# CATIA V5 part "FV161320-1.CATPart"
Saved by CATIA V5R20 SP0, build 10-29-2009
Part number: FV161320-1
Revision: ANY
Definition: UNKNOWN
Nomenclature: FV161320-1
Source: Unknown
Bounding box of the stored display mesh (mm): x -8 to 8, y -20 to 0, z -8 to 8
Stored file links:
  C:\Users\Utente\Desktop\IO LAVORO\3D X SITO CF\CUMSA\3D files FV\FV 161320\FV161320-1.CATPart
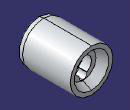
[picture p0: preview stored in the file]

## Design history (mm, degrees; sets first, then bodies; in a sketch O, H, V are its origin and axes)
Body1 "Cortar-Extruir1" (main body)
  Solid1: solid without history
